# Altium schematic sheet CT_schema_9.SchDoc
size 254 x 194 mm
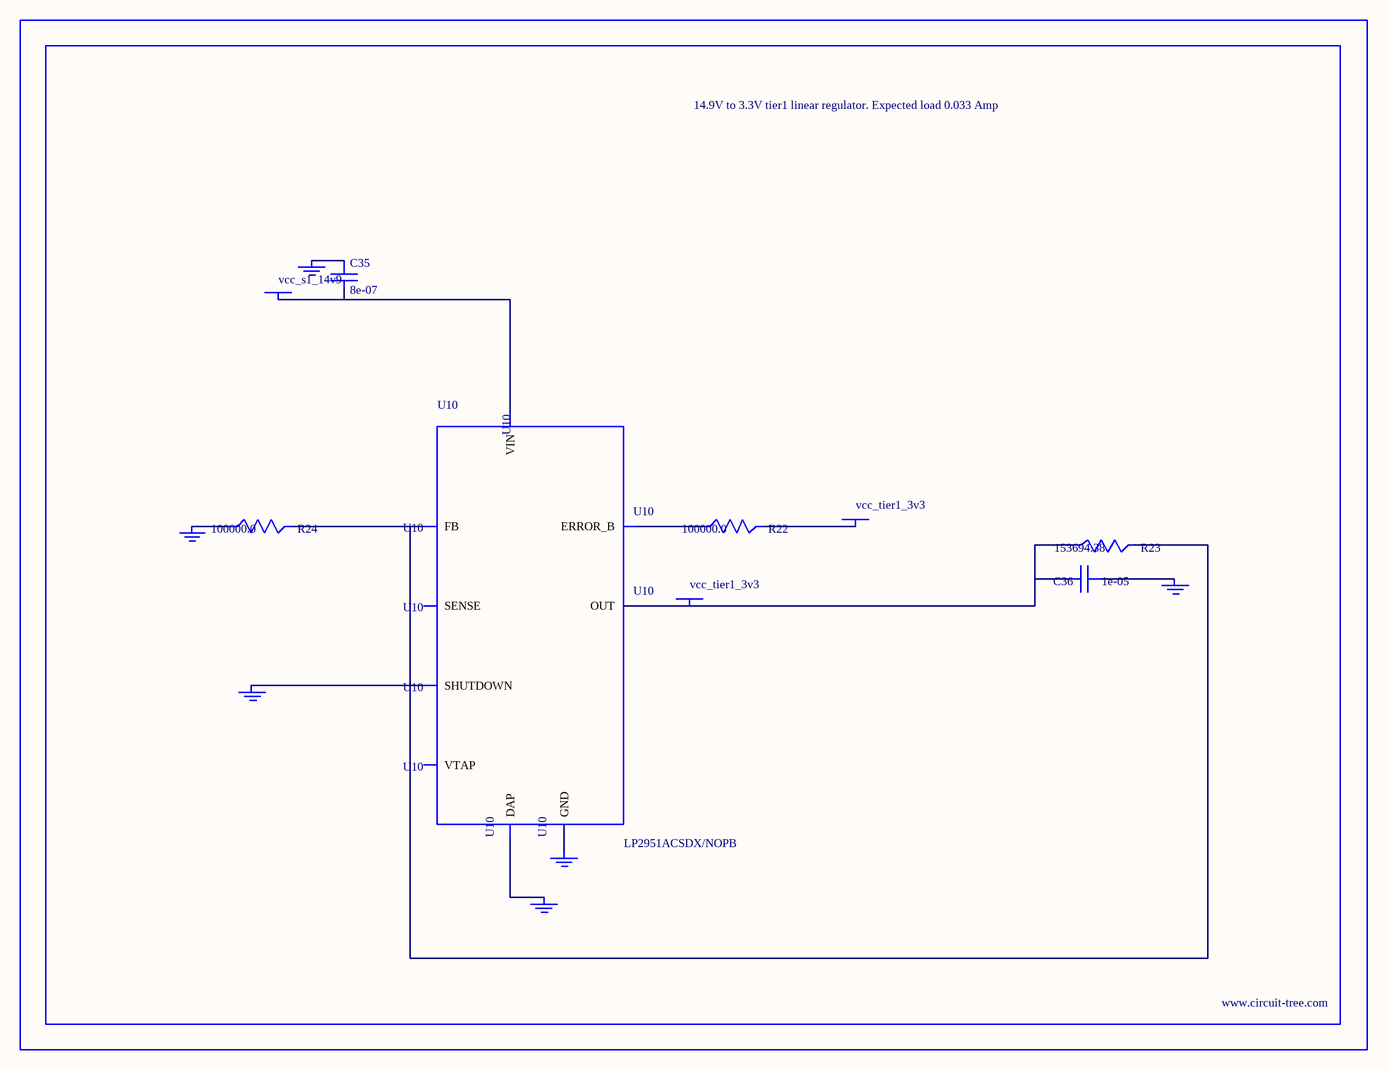
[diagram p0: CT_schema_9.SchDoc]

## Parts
BORDER8  (no value)
C35  8e-07  [R0603]
C36  1e-05  [C1210]
GND_INSTANCE_8_0  (no value)
GND_INSTANCE_8_1  (no value)
GND_INSTANCE_8_2  (no value)
GND_INSTANCE_8_3  (no value)
GND_INSTANCE_8_4  (no value)
GND_INSTANCE_8_5  (no value)
POWER_INSTANCE_8_0  vcc_tier1_3v3
POWER_INSTANCE_8_1  vcc_s1_14v9
POWER_INSTANCE_8_2  vcc_tier1_3v3
R22  100000.0  [R0603]
R23  153694.38  [R0603]
R24  100000.0  [R0603]
U10  LP2951ACSDX/NOPB  [WSON-8]

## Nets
NetC35_1: C35.1 GND_INSTANCE_8_3.0(GND)
NetC35_2: C35.2 POWER_INSTANCE_8_1.0(PWR) U10.8(VIN)
NetC36_1: C36.1 GND_INSTANCE_8_0.0(GND)
NetC36_2: C36.2 POWER_INSTANCE_8_2.0(PWR) R23.1 U10.1(OUT)
NetGND_INSTANCE_8_1_0: GND_INSTANCE_8_1.0(GND) U10.3(SHUTDOWN)
NetGND_INSTANCE_8_2_0: GND_INSTANCE_8_2.0(GND) R24.1
NetGND_INSTANCE_8_4_0: GND_INSTANCE_8_4.0(GND) U10.PAD(DAP)
NetGND_INSTANCE_8_5_0: GND_INSTANCE_8_5.0(GND) U10.4(GND)
NetPOWER_INSTANCE_8_0_0: POWER_INSTANCE_8_0.0(PWR) R22.2
NetR22_1: R22.1 U10.5(ERROR_B)
NetR23_2: R23.2 R24.2 U10.7(FB)

Not connected (* = marked no-connect by the designer): U10 2(SENSE) 6(VTAP)

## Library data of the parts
BORDER8 = BORDER_PAGE8
C35 = C35
C36 = GRM32DR61E106MA12L
GND_INSTANCE_8_0-GND_INSTANCE_8_5 = GND
POWER_INSTANCE_8_0-POWER_INSTANCE_8_2 = PWR
R22 R24 = RC0603JR-07100KL
R23 = R23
